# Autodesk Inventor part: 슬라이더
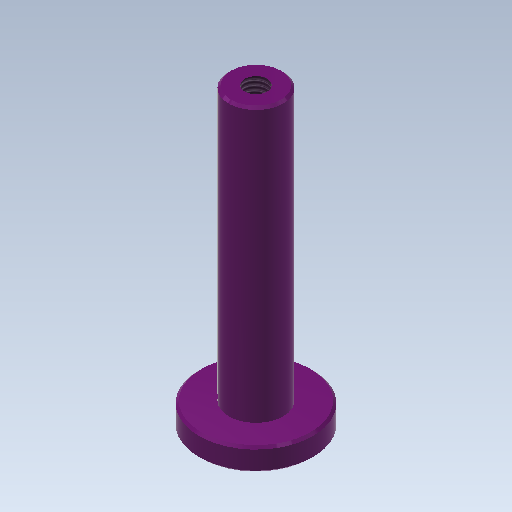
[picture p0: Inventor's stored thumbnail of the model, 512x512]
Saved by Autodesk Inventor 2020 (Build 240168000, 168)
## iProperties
Created: 2016-02
Part Number: 슬라이더
Material: 스테인리스강
Document SubType Name: Modeling
Designer: mduedu
Density: 8.08 g/cm^3
Appearance: 매끄러움 - 자주색
Author: mduedu
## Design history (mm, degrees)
sketch "스케치1"
  geometry: C1 r 12.5 at (0, 0); 1 further point
  constraints: 1 centre point, 1 coincident
  dimensions: "d0" = 25 diameter of C1
extrude "돌출1" new body sketch "스케치1" distance "d1" = 5; taper "d2" = 0 deg
sketch "스케치2"
  geometry: C1 r 6 at (0, 0); 1 further point
  constraints: 1 centre point, 1 coincident
  dimensions: "d3" = 12 diameter of C1
extrude "돌출2" join sketch "스케치2" distance "d4" = 60; taper "d5" = 0 deg
chamfer "모따기1" distance "d6" = 0.5; stored, may be unused: second distance "d7" = 2, angle "d8" = 45 deg
hole "구멍1" diameter "d11" = 4.917; stored, may be unused: countersink angle "d15" = 90 deg, drill point angle "d17" = 118 deg; dims "d9" = 10, "d10" = 10, "d12" = 10, "d13" = 4, "d14" = 2, "d16" = 12
chamfer "모따기2" distance "d18" = 0.5; stored, may be unused: second distance "d19" = 2, angle "d20" = 45 deg
node "솔리드1"
